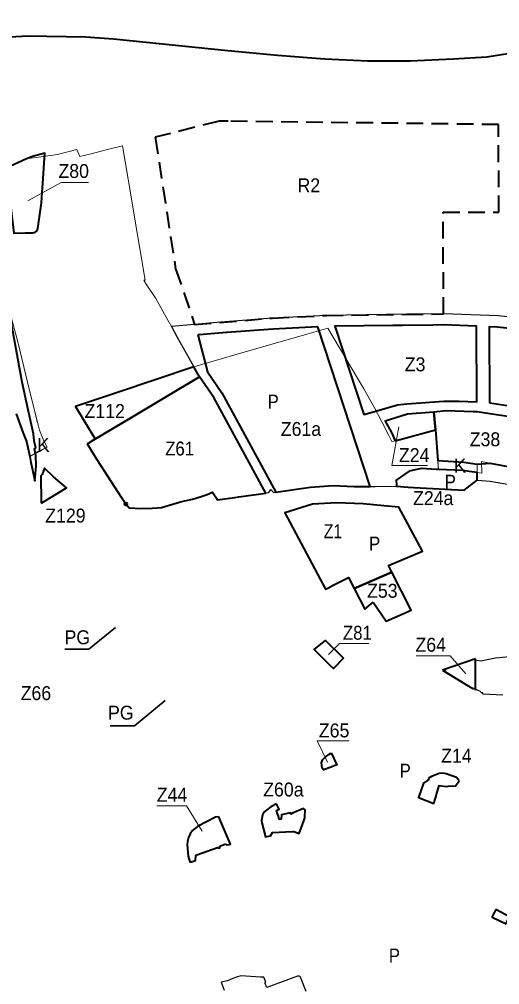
# Model space of a CAD drawing. Extents: x -650276 to -642489, y -1074425 to -1066658.
# Drawn here: x -647871 to -647044, y -1070685 to -1069023 of the extents above; entities that cross this region are included whole.
import ezdxf

# ---------------------------------------------------------------- set-up
doc = ezdxf.new("R2010")
doc.units = 0
doc.header["$LTSCALE"] = 9.6
doc.header["$PDMODE"] = 32
doc.header["$PDSIZE"] = 4.8
doc.linetypes.add('MEDIUM_DASHED', pattern=[4.5, 3, -1.5])
for name, color, linetype, lineweight in [('1', 7, 'Continuous', 13), ('42', 7, 'Continuous', 25), ('43', 7, 'Continuous', 13), ('44', 7, 'Continuous', 40), ('45', 7, 'Continuous', 40), ('46', 7, 'Continuous', 13), ('47', 7, 'Continuous', 13), ('60', 7, 'Continuous', 35), ('61', 7, 'MEDIUM_DASHED', 40), ('62', 7, 'Continuous', 35)]:
    doc.layers.add(name, color=color, linetype=linetype, lineweight=lineweight)

msp = doc.modelspace()

# ---------------------------------------------------------------- linework, layer by layer
at = {"layer": '1'}
for points in [[(-646952.56, -1069807.13), (-647075.22, -1069784.12), (-647074.31, -1069803.9), (-647096.39, -1069801.15), (-647107.04, -1069799.84), (-647148.9, -1069797.88), (-647151.57, -1069764.44), (-647152.73, -1069749.81), (-647154.33, -1069729.69), (-647223.66, -1069748.26), (-647229.389, -1069749.562), (-647234.25, -1069739.09), (-647246.42, -1069715.63), (-647259.62, -1069690.56), (-647277.43, -1069659.15), (-647339.58, -1069554.46), (-647371.83, -1069563.79), (-647375.71, -1069564.91), (-647499.63, -1069600.73), (-647570.37, -1069621.18), (-647573.15, -1069616.16), (-647600.89, -1069566.14), (-647606.53, -1069555.98), (-647615.07, -1069540.58), (-647635.69, -1069503.4), (-647652.23, -1069478.65), (-647656.18, -1069472.12), (-647653.86, -1069472.12), (-647662.58, -1069420.72), (-647671.74, -1069366.76), (-647678.84, -1069324.94), (-647693.15, -1069240.55), (-647723.69, -1069248.33), (-647746.96, -1069254.25), (-647766.21, -1069259.15), (-647771.45, -1069247.12), (-647805.14, -1069255.7)], [(-647805.14, -1069255.7), (-647858.37, -1069263.03), (-647942.68, -1069301.34)], [(-647873.43, -1069577.87), (-647852.44, -1069664.03), (-647846.91, -1069686.81), (-647845.85, -1069691.2), (-647841.26, -1069710.69), (-647837.67, -1069723.31), (-647835.76, -1069730.01), (-647830, -1069744.7), (-647828.61, -1069748.41), (-647822.54, -1069759.29), (-647829.37, -1069763.1), (-647834.61, -1069766.02), (-647840.49, -1069769.3), (-647842.55, -1069769.78), (-647852.63, -1069775.7), (-647858.44, -1069749.43), (-647875.82, -1069701.85)]]:
    msp.add_lwpolyline(points, dxfattribs=at)
at = {"layer": '42'}
for points in [[(-646986.633, -1069539.757), (-647046.325, -1069533.275), (-647140.008, -1069530.068), (-647204.293, -1069530.647), (-647341.697, -1069532.602), (-647434.969, -1069537.141), (-647523.931, -1069544.499), (-647568.792, -1069548.21), (-647608.81, -1069551.868), (-647598.735, -1069570.026), (-647573.15, -1069616.16), (-647570.37, -1069621.18), (-647570.37, -1069621.18), (-647701.61, -1069665.279), (-647774.11, -1069689.64), (-647740.74, -1069744.24), (-647742.36, -1069746.93), (-647752.32, -1069752.95), (-647753.7, -1069753.9), (-647745.84, -1069766.71), (-647687.45, -1069857.15), (-647681.51, -1069863.72), (-647661.79, -1069864.92), (-647641.78, -1069864.26), (-647625.83, -1069863.19), (-647593.07, -1069853.74), (-647572.63, -1069848.63), (-647559.47, -1069844.92), (-647547.12, -1069840.87), (-647538.34, -1069836.68), (-647531.33, -1069847.23), (-647529.5, -1069849.99), (-647492.76, -1069845.02), (-647441.19, -1069837.6), (-647437.46, -1069832.27), (-647433.32, -1069837.33), (-647369.3, -1069828.22), (-647330.46, -1069825.51), (-647294.38, -1069826.88)], [(-647235.49, -1069826.51), (-647205.603, -1069827.72), (-647191.66, -1069828.58), (-647201.106, -1069827.997), (-647191.66, -1069828.58), (-647104.741, -1069833.568), (-647082.145, -1069816.321), (-647074.72, -1069816.8), (-647060.029, -1069817.854), (-646993.81, -1069829.12)], [(-647294.38, -1069826.88), (-647270.09, -1069827.02), (-647258.143, -1069827.094), (-647235.49, -1069826.51)], [(-647005.97, -1070117.89), (-647044.19, -1070121.78), (-647051.14, -1070122.49), (-647070.7, -1070126.64), (-647075.81, -1070127.72), (-647090.2, -1070125.64), (-647133.96, -1070140.44), (-647136.65, -1070141.75), (-647137.99, -1070143.09), (-647137.96, -1070144.66), (-647136.09, -1070146.97), (-647132.95, -1070149.08), (-647097.63, -1070170.37), (-647077.39, -1070179.57), (-647076.83, -1070180.73), (-647075.42, -1070181.53), (-647073.42, -1070181.47), (-647073.35, -1070184.01), (-647061.2, -1070184.6), (-647038.31, -1070185.73)], [(-647377.04, -1070696.22), (-647386.39, -1070671.74), (-647388.31, -1070669.95), (-647391.74, -1070670.16), (-647418.28, -1070679.89), (-647444.78, -1070689.6), (-647447.31, -1070682.72), (-647447.76, -1070681.5), (-647446.22, -1070680.91), (-647447.58, -1070677.36), (-647449.69, -1070671.81), (-647455.17, -1070671.48), (-647489.21, -1070669.41), (-647496.64, -1070671.93), (-647503.3, -1070674.3), (-647512.51, -1070677.98), (-647523.27, -1070680.11), (-647518.19, -1070693.93)]]:
    msp.add_lwpolyline(points, dxfattribs=at)
at = {"layer": '44'}
for points in [[(-647065.688, -1069087.73), (-646978.92, -1069073.93), (-646929.186, -1069052.925), (-646880.163, -1069024.903), (-646829.104, -1068987.917), (-646782.784, -1068941.581), (-646741.85, -1068895.719), (-646673.05, -1068812.491), (-646618.655, -1068742.359), (-646617.991, -1068741.504)], [(-647886.615, -1069053.052), (-647856.541, -1069051.548), (-647756.441, -1069053.207), (-647708.401, -1069056.275), (-647511.94, -1069076.703), (-647426.417, -1069084.624), (-647344.902, -1069091.02), (-647270.522, -1069094.255), (-647197.498, -1069094.255), (-647123.648, -1069091.043), (-647065.688, -1069087.73)], [(-647865.69, -1069647.32), (-647887.649, -1069528.021), (-647887.087, -1069527.229)], [(-647842.438, -1069760.647), (-647845.086, -1069748.753), (-647846.484, -1069736.663), (-647855.158, -1069695.232), (-647865.69, -1069647.32)], [(-647875.82, -1069701.85), (-647864.19, -1069735.12), (-647858.44, -1069749.43), (-647852.63, -1069775.7), (-647850.66, -1069785.74), (-647849.165, -1069793.367), (-647843.74, -1069817.63), (-647841.402, -1069792.351)], [(-647841.402, -1069792.351), (-647842.489, -1069773.282), (-647842.622, -1069770.956), (-647843.337, -1069769.013), (-647843.443, -1069768.293), (-647843.458, -1069768.256), (-647843.449, -1069768.252), (-647844.371, -1069761.991), (-647842.438, -1069760.647)]]:
    msp.add_lwpolyline(points, dxfattribs=at)
for points in [[(-647860.52, -1069390.72), (-647848.24, -1069390.65), (-647845.25, -1069390.07), (-647843.41, -1069389.23), (-647841.81, -1069387.99), (-647840.42, -1069386.51), (-647839.4, -1069384.73), (-647838.79, -1069382.86), (-647836.2, -1069362.68), (-647832.29, -1069338.58), (-647832.29, -1069338.58), (-647831.19, -1069320.69), (-647830.23, -1069305.38), (-647826.928, -1069253.199), (-647848.17, -1069259.21), (-647858.37, -1069263.03), (-647893.553, -1069279.017), (-647880.326, -1069390.832)], [(-647312.485, -1070122.583), (-647329.932, -1070140.465), (-647334.81, -1070135.73), (-647357.4, -1070113.69), (-647359.8, -1070111.34), (-647362.87, -1070107.74), (-647343.454, -1070092.368)]]:
    msp.add_lwpolyline(points, close=True, dxfattribs=at)
at = {"layer": '44', "lineweight": 13}
for points in [[(-647751.811, -1069303.761), (-647798.61, -1069303.761), (-647856.005, -1069335.572)], [(-647751.811, -1069303.761), (-647798.61, -1069303.761), (-647856.005, -1069335.572)], [(-647268.839, -1070097.432), (-647319.538, -1070097.432), (-647338.315, -1070116.223)], [(-647268.839, -1070097.432), (-647319.538, -1070097.432), (-647338.315, -1070116.223)]]:
    msp.add_lwpolyline(points, dxfattribs=at)
at = {"layer": '45'}
for p, q in [((-647085.131, -1070123.926), (-647142.227, -1070143.236)), ((-647085.131, -1070123.926), (-647142.227, -1070143.236)), ((-647085.131, -1070177.975), (-647085.131, -1070123.926)), ((-647085.131, -1070177.975), (-647085.131, -1070123.926))]:
    msp.add_line(p, q, dxfattribs=at)
for points in [[(-647356.899, -1069552.034), (-647433.779, -1069556.106), (-647433.779, -1069556.106), (-647513.66, -1069562.249), (-647514.067, -1069562.282), (-647560.836, -1069566.036), (-647563.104, -1069566.28)], [(-647369.3, -1069828.22), (-647330.46, -1069825.51), (-647294.38, -1069826.88), (-647270.09, -1069827.02), (-647266.581, -1069827.042), (-647356.899, -1069552.034)], [(-647563.104, -1069566.28), (-647546.777, -1069629.901), (-647521.943, -1069665.763)], [(-647570.37, -1069621.18), (-647701.61, -1069665.279), (-647774.11, -1069689.64), (-647740.74, -1069744.24), (-647742.36, -1069746.93), (-647674.901, -1069706.701)], [(-647570.37, -1069621.18), (-647701.61, -1069665.279), (-647774.11, -1069689.64), (-647740.74, -1069744.24), (-647742.36, -1069746.93), (-647674.901, -1069706.701)], [(-647674.901, -1069706.701), (-647560.36, -1069638.39), (-647570.37, -1069621.18)], [(-647674.901, -1069706.701), (-647560.36, -1069638.39), (-647570.37, -1069621.18)], [(-647560.36, -1069638.39), (-647674.901, -1069706.701), (-647742.36, -1069746.93)], [(-647446.322, -1069838.338), (-647535.588, -1069674.163), (-647560.36, -1069638.39)], [(-647521.943, -1069665.763), (-647428.993, -1069836.714), (-647369.3, -1069828.22)], [(-647742.36, -1069746.93), (-647752.32, -1069752.95), (-647753.7, -1069753.9)], [(-647753.7, -1069753.9), (-647751.66, -1069757.12), (-647745.84, -1069766.71), (-647737.17, -1069780.85), (-647700.58, -1069837.2), (-647687.45, -1069857.15), (-647681.51, -1069863.72)], [(-647641.78, -1069864.26), (-647625.83, -1069863.19), (-647593.07, -1069853.74), (-647583.62, -1069851.13), (-647572.63, -1069848.63), (-647559.47, -1069844.92), (-647547.12, -1069840.87), (-647538.34, -1069836.68), (-647536.82, -1069838.87), (-647531.33, -1069847.23), (-647529.5, -1069849.99), (-647500.03, -1069846.28), (-647492.76, -1069845.02), (-647446.322, -1069838.338)], [(-647681.51, -1069863.72), (-647661.79, -1069864.92), (-647641.78, -1069864.26)], [(-647142.227, -1070143.236), (-647097.63, -1070170.37), (-647088.916, -1070175.672)], [(-647142.227, -1070143.236), (-647097.63, -1070170.37), (-647088.916, -1070175.672)], [(-647167.03, -1070329.81), (-647165.36, -1070331.59), (-647174.81, -1070338.01), (-647183.55, -1070362.35), (-647156.9, -1070372.69)], [(-647113.37, -1070333.96), (-647118.28, -1070328.29), (-647135.94, -1070321.54), (-647140.83, -1070320.47), (-647147.66, -1070321.04), (-647161.17, -1070326.29), (-647167.03, -1070329.81)], [(-647156.9, -1070372.69), (-647154.31, -1070363.46), (-647151.09, -1070353.15), (-647147.6, -1070341.95), (-647144.57, -1070342.42), (-647139.84, -1070343.16), (-647135.62, -1070343.32), (-647132.49, -1070342.91)], [(-647132.49, -1070342.91), (-647119.88, -1070342.1), (-647116.03, -1070337.68), (-647113.37, -1070333.96)]]:
    msp.add_lwpolyline(points, dxfattribs=at)
for points in [[(-647251.002, -1069695.852), (-647219.628, -1069686.746), (-647203.374, -1069684.716), (-647139.649, -1069679.961), (-647113.255, -1069679.966), (-647082.761, -1069681.399), (-647083.356, -1069551.018), (-647140.247, -1069549.071), (-647158.572, -1069549.252), (-647211.05, -1069549.77), (-647227.623, -1069550.23), (-647327.682, -1069551.263), (-647277.71, -1069703.421)], [(-647251.002, -1069695.852), (-647219.628, -1069686.746), (-647203.374, -1069684.716), (-647139.649, -1069679.961), (-647113.255, -1069679.966), (-647082.761, -1069681.399), (-647083.356, -1069551.018), (-647140.247, -1069549.071), (-647158.572, -1069549.252), (-647211.05, -1069549.77), (-647227.623, -1069550.23), (-647327.682, -1069551.263), (-647277.71, -1069703.421)], [(-647060.7, -1069683.894), (-647061.304, -1069551.773), (-647047.648, -1069552.245), (-646944.168, -1069563.743), (-646846, -1069575), (-646863, -1069714)], [(-647060.7, -1069683.894), (-647061.304, -1069551.773), (-647047.648, -1069552.245), (-646944.168, -1069563.743), (-646846, -1069575), (-646863, -1069714)], [(-647223.66, -1069748.26), (-647154.33, -1069729.69), (-647156.782, -1069698.901), (-647202.181, -1069702.678), (-647240.994, -1069714.513), (-647230.16, -1069734.42)], [(-647223.66, -1069748.26), (-647154.33, -1069729.69), (-647156.782, -1069698.901), (-647202.181, -1069702.678), (-647240.994, -1069714.513), (-647230.16, -1069734.42)], [(-647060.617, -1069702.116), (-647082.682, -1069698.791), (-647089.456, -1069698.579), (-647135.585, -1069697.137), (-647156.782, -1069698.901), (-647154.33, -1069729.69), (-647150.138, -1069782.334), (-647105.334, -1069785.168), (-647082.271, -1069788.81), (-647060.23, -1069786.932), (-646952.56, -1069807.13), (-646980.4, -1069746.98), (-646998.56, -1069711.443)], [(-647833.172, -1069855.944), (-647833.172, -1069855.944), (-647831.62, -1069854.99), (-647789.55, -1069829.12), (-647811.83, -1069810.39), (-647827.16, -1069795.32), (-647831.32, -1069806.56), (-647833.91, -1069808.91), (-647833.2, -1069854.15)], [(-647196.616, -1069800.068), (-647199.65, -1069800.69), (-647221.87, -1069816.21), (-647221.28, -1069824.74), (-647221.14, -1069826.761), (-647201.106, -1069827.997), (-647191.66, -1069828.58), (-647104.741, -1069833.568), (-647082.145, -1069816.321), (-647082.206, -1069802.916), (-647096.39, -1069801.15), (-647107.04, -1069799.84), (-647148.9, -1069797.88), (-647152.39, -1069797.7), (-647178.73, -1069796.4)], [(-647365.866, -1069857.774), (-647413.461, -1069872.442), (-647343.28, -1070003.81), (-647339.69, -1070001.95), (-647330.5, -1069997.19), (-647304.05, -1069983.79), (-647294.257, -1070002.745), (-647242.254, -1069980.33), (-647229.096, -1069974.658), (-647235, -1069963), (-647176.499, -1069938.333), (-647205.781, -1069883.796), (-647217.177, -1069862.57), (-647243.231, -1069860.34), (-647278.525, -1069857.002), (-647323.794, -1069855.468)], [(-647365.866, -1069857.774), (-647413.461, -1069872.442), (-647343.28, -1070003.81), (-647339.69, -1070001.95), (-647330.5, -1069997.19), (-647304.05, -1069983.79), (-647294.257, -1070002.745), (-647242.254, -1069980.33), (-647229.096, -1069974.658), (-647235, -1069963), (-647176.499, -1069938.333), (-647205.781, -1069883.796), (-647217.177, -1069862.57), (-647243.231, -1069860.34), (-647278.525, -1069857.002), (-647323.794, -1069855.468)], [(-647261.27, -1070026.12), (-647238.99, -1070059.05), (-647195.933, -1070040.107), (-647229.096, -1069974.658), (-647294.257, -1070002.745), (-647276, -1070038.08)], [(-647261.27, -1070026.12), (-647238.99, -1070059.05), (-647195.933, -1070040.107), (-647229.096, -1069974.658), (-647294.257, -1070002.745), (-647276, -1070038.08)], [(-647333.87, -1070285.66), (-647324.11, -1070306.21), (-647324.94, -1070306.63), (-647327.18, -1070307.52), (-647333.97, -1070310.22), (-647346.97, -1070315.05), (-647349, -1070312), (-647350.67, -1070302.55), (-647348.677, -1070297.894), (-647345.27, -1070293.99), (-647343.9, -1070292.96), (-647337.56, -1070288.43), (-647334.91, -1070286.51)], [(-647333.87, -1070285.66), (-647324.11, -1070306.21), (-647324.94, -1070306.63), (-647327.18, -1070307.52), (-647333.97, -1070310.22), (-647346.97, -1070315.05), (-647349, -1070312), (-647350.67, -1070302.55), (-647348.677, -1070297.894), (-647345.27, -1070293.99), (-647343.9, -1070292.96), (-647337.56, -1070288.43), (-647334.91, -1070286.51)], [(-647427.8, -1070373.32), (-647437.76, -1070378.66), (-647449.69, -1070387.83), (-647452.17, -1070392.38), (-647453.71, -1070401.81), (-647453.35, -1070406.09), (-647450.51, -1070416.96), (-647446.93, -1070429.99), (-647438.45, -1070428.47), (-647434.85, -1070422.64), (-647423.38, -1070421.87), (-647412.51, -1070421.5), (-647400.41, -1070421.08), (-647398.21, -1070421.15), (-647388.6, -1070424.24), (-647381.11, -1070402.45), (-647379.3, -1070397.57), (-647378.49, -1070383.91), (-647381.65, -1070381.45), (-647400.22, -1070389.64), (-647403.27, -1070390.91), (-647404, -1070388.84), (-647409.36, -1070390.24), (-647419.08, -1070392.52), (-647419.68, -1070399.59), (-647423.58, -1070400.59), (-647424.54, -1070394.78), (-647425.99, -1070390.47), (-647427.96, -1070384.64), (-647423.57, -1070382.64)], [(-647427.8, -1070373.32), (-647437.76, -1070378.66), (-647449.69, -1070387.83), (-647452.17, -1070392.38), (-647453.71, -1070401.81), (-647453.35, -1070406.09), (-647450.51, -1070416.96), (-647446.93, -1070429.99), (-647438.45, -1070428.47), (-647434.85, -1070422.64), (-647423.38, -1070421.87), (-647412.51, -1070421.5), (-647400.41, -1070421.08), (-647398.21, -1070421.15), (-647388.6, -1070424.24), (-647381.11, -1070402.45), (-647379.3, -1070397.57), (-647378.49, -1070383.91), (-647381.65, -1070381.45), (-647400.22, -1070389.64), (-647403.27, -1070390.91), (-647404, -1070388.84), (-647409.36, -1070390.24), (-647419.08, -1070392.52), (-647419.68, -1070399.59), (-647423.58, -1070400.59), (-647424.54, -1070394.78), (-647425.99, -1070390.47), (-647427.96, -1070384.64), (-647423.57, -1070382.64)], [(-647515.73, -1070442.32), (-647514.23, -1070444.18), (-647509.22, -1070443.62), (-647506.95, -1070442.71), (-647522.54, -1070406.51), (-647527.1, -1070395.72), (-647533.1, -1070396.26), (-647564.01, -1070412.59), (-647572.37, -1070419.41), (-647576.48, -1070425.09), (-647579.22, -1070431.05), (-647581.04, -1070438.4), (-647581.54, -1070443.7), (-647580.1, -1070463.69), (-647576.92, -1070473), (-647574.28, -1070473.46), (-647567.32, -1070470.66), (-647566.55, -1070462.22), (-647565.11, -1070461.12), (-647529.74, -1070448.27), (-647528.28, -1070449.87), (-647525.54, -1070448.89), (-647525.45, -1070446.21)], [(-647515.73, -1070442.32), (-647514.23, -1070444.18), (-647509.22, -1070443.62), (-647506.95, -1070442.71), (-647522.54, -1070406.51), (-647527.1, -1070395.72), (-647533.1, -1070396.26), (-647564.01, -1070412.59), (-647572.37, -1070419.41), (-647576.48, -1070425.09), (-647579.22, -1070431.05), (-647581.04, -1070438.4), (-647581.54, -1070443.7), (-647580.1, -1070463.69), (-647576.92, -1070473), (-647574.28, -1070473.46), (-647567.32, -1070470.66), (-647566.55, -1070462.22), (-647565.11, -1070461.12), (-647529.74, -1070448.27), (-647528.28, -1070449.87), (-647525.54, -1070448.89), (-647525.45, -1070446.21)], [(-647032.738, -1070579.83), (-647029.168, -1070572.13), (-647028.248, -1070572.63), (-647025.868, -1070568.26), (-647049.248, -1070555.64), (-647050.098, -1070555.74), (-647050.868, -1070556.59), (-647052.498, -1070559.7), (-647056.518, -1070567.41), (-647056.528, -1070568.32), (-647055.518, -1070569.07)]]:
    msp.add_lwpolyline(points, close=True, dxfattribs=at)
msp.add_point((-647687.45, -1069857.15), dxfattribs=at)
at = {"layer": '46'}
for points in [[(-647167.693, -1069791.112), (-647229.126, -1069791.112), (-647217.012, -1069724.439)], [(-647167.693, -1069791.112), (-647229.126, -1069791.112), (-647217.012, -1069724.439)], [(-647187.627, -1070118.571), (-647128.949, -1070118.571), (-647102.191, -1070149.577)], [(-647187.627, -1070118.571), (-647128.949, -1070118.571), (-647102.191, -1070149.577)], [(-647302.639, -1070264.673), (-647358.031, -1070264.673), (-647340.193, -1070301.786)], [(-647302.639, -1070264.673), (-647358.031, -1070264.673), (-647340.193, -1070301.786)], [(-647634.056, -1070376.951), (-647582.888, -1070376.951), (-647556.111, -1070420.553)], [(-647634.056, -1070376.951), (-647582.888, -1070376.951), (-647556.111, -1070420.553)]]:
    msp.add_lwpolyline(points, dxfattribs=at)
at = {"layer": '47'}
for p, q in [((-647150.141, -1069782.334), (-647148.9, -1069797.88)), ((-647107.04, -1069799.84), (-647096.39, -1069801.15))]:
    msp.add_line(p, q, dxfattribs=at)
msp.add_lwpolyline([(-647845.086, -1069748.753), (-647842.438, -1069760.647), (-647844.371, -1069761.991), (-647843.337, -1069769.013), (-647822.54, -1069759.29), (-647830, -1069744.7), (-647835.76, -1069730.01), (-647845.85, -1069691.2), (-647852.44, -1069664.03), (-647873.43, -1069577.87), (-647887.087, -1069527.229), (-647865.69, -1069647.32), (-647855.158, -1069695.232), (-647846.484, -1069736.663)], close=True, dxfattribs=at)
for points in [[(-647082.271, -1069788.81), (-647105.334, -1069785.168), (-647105.334, -1069785.168), (-647150.138, -1069782.334)], [(-647148.9, -1069797.88), (-647148.9, -1069797.88), (-647107.04, -1069799.84)], [(-647096.39, -1069801.15), (-647096.39, -1069801.15), (-647082.206, -1069802.917), (-647082.271, -1069788.81)]]:
    msp.add_lwpolyline(points, dxfattribs=at)
at = {"layer": '60'}
for points in [[(-647792.254, -1070107.298), (-647750.945, -1070107.298), (-647704.94, -1070069.715)], [(-647792.254, -1070107.298), (-647750.945, -1070107.298), (-647704.94, -1070069.715)], [(-647714.329, -1070238.836), (-647672.08, -1070238.836), (-647619.504, -1070195.616)], [(-647714.329, -1070238.836), (-647672.08, -1070238.836), (-647619.504, -1070195.616)]]:
    msp.add_lwpolyline(points, dxfattribs=at)
at = {"layer": '61'}
msp.add_lwpolyline([(-647045.7, -1069204.106), (-647511.107, -1069198.223), (-647526.615, -1069198.093), (-647636.743, -1069226.014), (-647601.568, -1069452.14), (-647568.792, -1069548.21), (-647434.969, -1069537.141), (-647341.697, -1069532.602), (-647204.293, -1069530.647), (-647140.334, -1069530.057), (-647141.134, -1069354.872), (-647045.123, -1069355.003)], close=True, dxfattribs=at)

# ---------------------------------------------------------------- texts
at = {"layer": '43'}
for p in [(-647839.874, -1069767.492), (-647122.713, -1069803.226)]:
    msp.add_text('K', height=24, dxfattribs=at).set_placement(p)
at = {"layer": '44'}
for s, width, p in [('Z80', 0.95, (-647803.311, -1069296.044)), ('Z80', 0.95, (-647803.311, -1069296.044)), ('Z81', 0.9, (-647313.531, -1070090.851)), ('Z81', 0.9, (-647313.531, -1070090.851))]:
    msp.add_text(s, height=24, dxfattribs=dict(at, width=width)).set_placement(p)
at = {"layer": '46'}
for s, width, p in [('Z3', 0.95, (-647207.094, -1069628.872)), ('Z3', 0.95, (-647207.094, -1069628.872)), ('Z112', 0.95, (-647758.383, -1069709.22)), ('Z112', 0.95, (-647758.383, -1069709.22)), ('Z61a', 0.95, (-647420.53, -1069740.066)), ('Z38', 0.95, (-647095.223, -1069757.854)), ('Z38', 0.95, (-647095.223, -1069757.854)), ('Z61', 0.9, (-647619.576, -1069773.738)), ('Z24', 0.95, (-647217.069, -1069785.057)), ('Z24', 0.95, (-647217.069, -1069785.057)), ('Z24a', 0.95, (-647192.847, -1069859.131)), ('Z129', 0.95, (-647826.051, -1069889.189)), ('Z1', 0.85, (-647346.649, -1069916.072)), ('Z1', 0.85, (-647346.649, -1069916.072)), ('Z53', 0.95, (-647272.017, -1070018.639)), ('Z53', 0.95, (-647272.017, -1070018.639)), ('Z64', 0.95, (-647188.663, -1070111.521)), ('Z64', 0.95, (-647188.663, -1070111.521)), ('Z66', 0.95, (-647868.376, -1070194.801)), ('Z65', 0.95, (-647355.018, -1070259.014)), ('Z65', 0.95, (-647355.018, -1070259.014)), ('Z14', 0.95, (-647144.477, -1070302.522)), ('Z44', 0.95, (-647634.087, -1070369.724)), ('Z44', 0.95, (-647634.087, -1070369.724)), ('Z60a', 0.95, (-647450.804, -1070360.702))]:
    msp.add_text(s, height=24, dxfattribs=dict(at, width=width)).set_placement(p)
at = {"layer": '60'}
for s, width, p in [('P', 0.9, (-647443.274, -1069692.913)), ('P', 0.9, (-647443.274, -1069692.913)), ('P', 0.9, (-647138.27, -1069830.996)), ('P', 0.9, (-647138.27, -1069830.996)), ('P', 0.9, (-647268.59, -1069937.47)), ('P', 0.9, (-647268.59, -1069937.47)), ('PG', 0.95, (-647792.805, -1070098.685)), ('PG', 0.95, (-647792.805, -1070098.685)), ('PG', 0.95, (-647717.94, -1070228.451)), ('PG', 0.95, (-647717.94, -1070228.451)), ('P', 0.9, (-647215.907, -1070328.431)), ('P', 0.9, (-647215.907, -1070328.431)), ('P', 0.9, (-647234.488, -1070646.552))]:
    msp.add_text(s, height=24, dxfattribs=dict(at, width=width)).set_placement(p)
at = {"layer": '62', "width": 0.95}
msp.add_text('R2', height=24, dxfattribs=at).set_placement((-647391.654, -1069320.724))
msp.add_text('R2', height=24, dxfattribs=at).set_placement((-647391.654, -1069320.724))

doc.saveas('drawing.dxf')
